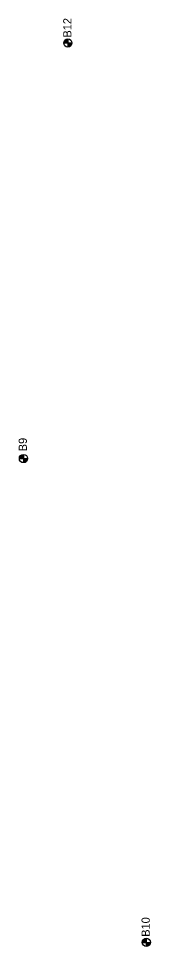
# Model space of a CAD drawing. Extents: x 345549 to 379569, y 127949 to 230467.
# Drawn here: x 361429 to 361590, y 132602 to 133734 of the extents above; entities that cross this region are included whole.
import ezdxf

# ---------------------------------------------------------------- set-up
doc = ezdxf.new("R2010")
doc.units = 0
for name, color, linetype in [('E_SOIL_BORE1 [KAPUR_CADDS_LEVELS]', 7, 'Continuous'), ('E_SOIL_BORE2 [KAPUR_CADDS_LEVELS]', 7, 'Continuous'), ('P_MARK', 7, 'Continuous')]:
    doc.layers.add(name, color=color, linetype=linetype)

msp = doc.modelspace()

# ---------------------------------------------------------------- linework, layer by layer
at = {"layer": 'P_MARK'}
for p, q in [((361484, 133703.8), (361494, 133703.8)), ((361489, 133708.8), (361489, 133698.8)), ((361430, 133197.2), (361440, 133197.2)), ((361435, 133202.2), (361435, 133192.2)), ((361579.5, 132607.5), (361589.5, 132607.5)), ((361584.5, 132612.5), (361584.5, 132602.5))]:
    msp.add_line(p, q, dxfattribs=at)
for centre in [(361489, 133703.8), (361435, 133197.2), (361584.5, 132607.5)]:
    msp.add_circle(centre, 5, dxfattribs=at)
for centre, radius, start, end in [((361489, 133703.8), 4.5, 89.9869, 179.9869), ((361489, 133703.8), 4, 89.9869, 179.9869), ((361489, 133703.8), 3.5, 89.9869, 179.9869), ((361489, 133703.8), 3, 89.9869, 179.9869), ((361489, 133703.8), 2.5, 89.9869, 179.9869), ((361489, 133703.8), 2, 89.9869, 179.9869), ((361489, 133703.8), 1.5, 89.9869, 179.9869), ((361489, 133703.8), 1, 89.9869, 179.9869), ((361489, 133703.8), 0.5, 89.9869, 179.9869), ((361489, 133703.8), 4.5, 269.9869, 359.9869), ((361489, 133703.8), 4, 269.9869, 359.9869), ((361489, 133703.8), 3.5, 269.9869, 359.9869), ((361489, 133703.8), 3, 269.9869, 359.9869), ((361489, 133703.8), 2.5, 269.9869, 359.9869), ((361489, 133703.8), 2, 269.9869, 359.9869), ((361489, 133703.8), 1.5, 269.9869, 359.9869), ((361489, 133703.8), 1, 269.9869, 359.9869), ((361489, 133703.8), 0.5, 269.9869, 359.9869), ((361435, 133197.2), 4.5, 89.9869, 179.9869), ((361435, 133197.2), 4, 89.9869, 179.9869), ((361435, 133197.2), 3.5, 89.9869, 179.9869), ((361435, 133197.2), 3, 89.9869, 179.9869), ((361435, 133197.2), 2.5, 89.9869, 179.9869), ((361435, 133197.2), 2, 89.9869, 179.9869), ((361435, 133197.2), 1.5, 89.9869, 179.9869), ((361435, 133197.2), 1, 89.9869, 179.9869), ((361435, 133197.2), 0.5, 89.9869, 179.9869), ((361435, 133197.2), 4.5, 269.9869, 359.9869), ((361435, 133197.2), 4, 269.9869, 359.9869), ((361435, 133197.2), 3.5, 269.9869, 359.9869), ((361435, 133197.2), 3, 269.9869, 359.9869), ((361435, 133197.2), 2.5, 269.9869, 359.9869), ((361435, 133197.2), 2, 269.9869, 359.9869), ((361435, 133197.2), 1.5, 269.9869, 359.9869), ((361435, 133197.2), 1, 269.9869, 359.9869), ((361435, 133197.2), 0.5, 269.9869, 359.9869), ((361584.5, 132607.5), 4.5, 89.9869, 179.9869), ((361584.5, 132607.5), 4, 89.9869, 179.9869), ((361584.5, 132607.5), 3.5, 89.9869, 179.9869), ((361584.5, 132607.5), 3, 89.9869, 179.9869), ((361584.5, 132607.5), 2.5, 89.9869, 179.9869), ((361584.5, 132607.5), 2, 89.9869, 179.9869), ((361584.5, 132607.5), 1.5, 89.9869, 179.9869), ((361584.5, 132607.5), 1, 89.9869, 179.9869), ((361584.5, 132607.5), 0.5, 89.9869, 179.9869), ((361584.5, 132607.5), 4.5, 269.9869, 359.9869), ((361584.5, 132607.5), 4, 269.9869, 359.9869), ((361584.5, 132607.5), 3.5, 269.9869, 359.9869), ((361584.5, 132607.5), 3, 269.9869, 359.9869), ((361584.5, 132607.5), 2.5, 269.9869, 359.9869), ((361584.5, 132607.5), 2, 269.9869, 359.9869), ((361584.5, 132607.5), 1.5, 269.9869, 359.9869), ((361584.5, 132607.5), 1, 269.9869, 359.9869), ((361584.5, 132607.5), 0.5, 269.9869, 359.9869)]:
    msp.add_arc(centre, radius, start, end, dxfattribs=at)

# ---------------------------------------------------------------- texts
at = {"layer": 'E_SOIL_BORE1 [KAPUR_CADDS_LEVELS]'}
msp.add_text('B10', height=10, rotation=89.9869, dxfattribs=at).set_placement((361588.7, 132614.3))
at = {"layer": 'E_SOIL_BORE2 [KAPUR_CADDS_LEVELS]'}
for s, p in [('B12', (361493.4, 133710.4)), ('B9', (361439.2, 133206.1))]:
    msp.add_text(s, height=10, rotation=89.9869, dxfattribs=at).set_placement(p)

doc.saveas('drawing.dxf')
